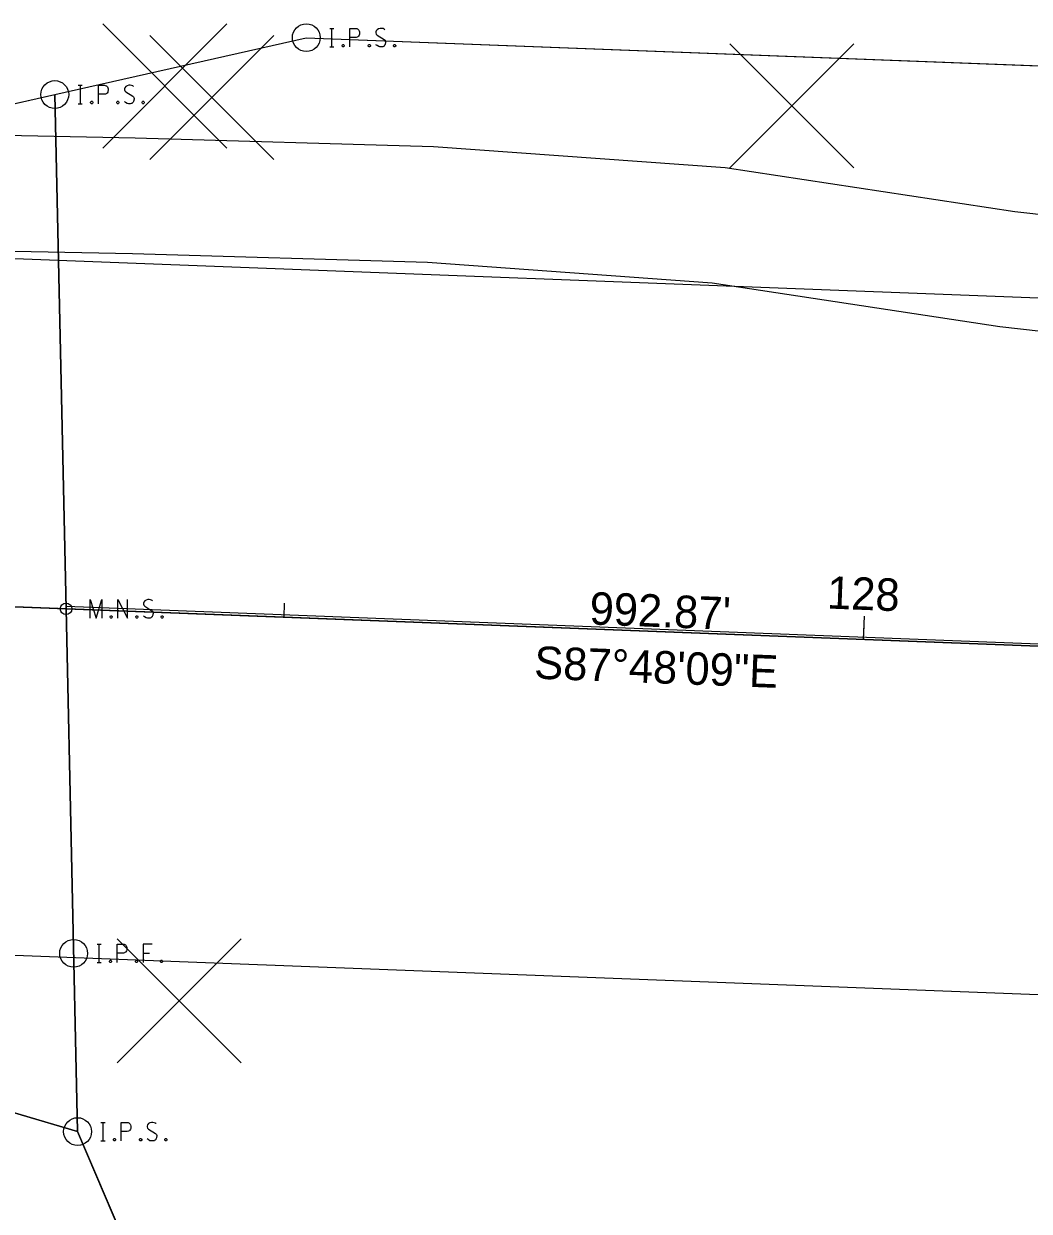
# Model space of a CAD drawing. Extents: x 2003596 to 2006933, y 570827 to 573780.
# Drawn here: x 2005461.8 to 2005548.5, y 572566.7 to 572669.1 of the extents above; entities that cross this region are included whole.
import ezdxf

# ---------------------------------------------------------------- set-up
doc = ezdxf.new("R2010")
doc.units = 0
for name, color, linetype in [('DT_X_Contour_Major', 7, 'Continuous'), ('DT_X_Spot_Elev', 7, 'Continuous'), ('DT_X_TIN_Hull', 7, 'Continuous'), ('GE_X_Alignment', 7, 'Continuous'), ('GE_X_Alignment_1000_Bearings', 7, 'Continuous'), ('GE_X_Alignment_1000_Distances', 7, 'Continuous'), ('GE_X_Alignment_100_Bearings', 7, 'Continuous'), ('GE_X_Alignment_100_Distances', 7, 'Continuous'), ('GE_X_Alignment_100_Stations', 7, 'Continuous'), ('GE_X_Alignment_500_Bearings', 7, 'Continuous'), ('GE_X_Alignment_500_Distances', 7, 'Continuous'), ('GE_X_Alignment_500_Stations', 7, 'Continuous'), ('RW_X_CL', 7, 'Continuous'), ('RW_X_Esmt_SH', 7, 'Continuous'), ('SC_Scratch10', 7, 'Continuous'), ('SV_P_Mon_Cells_Set', 7, 'Continuous'), ('SV_X_Mon_Cells_Found', 7, 'Continuous'), ('UT_X_Overhead_Electric', 7, 'Continuous'), ('UT_X_Overhead_Telecom', 7, 'Continuous'), ('UT_X_Telecom', 7, 'Continuous')]:
    doc.layers.add(name, color=color, linetype=linetype)

msp = doc.modelspace()

# ---------------------------------------------------------------- linework, layer by layer
at = {"layer": 'DT_X_Contour_Major'}
for points in [[(2005467.51, 572617.87), (2005467.51, 572619.47), (2005468.02, 572617.87), (2005468.51, 572619.47), (2005468.51, 572617.87)], [(2005469.88, 572617.87), (2005469.88, 572619.47), (2005470.71, 572617.87), (2005470.71, 572619.47)], [(2005472.86, 572619.35), (2005472.84, 572619.38), (2005472.8, 572619.41), (2005472.71, 572619.44), (2005472.58, 572619.47), (2005472.5, 572619.47), (2005472.46, 572619.47), (2005472.32, 572619.43), (2005472.2, 572619.35), (2005472.12, 572619.25), (2005472.1, 572619.15), (2005472.1, 572619.08), (2005472.12, 572618.98), (2005472.21, 572618.89), (2005472.82, 572618.51), (2005472.87, 572618.46), (2005472.89, 572618.41), (2005472.92, 572618.33), (2005472.92, 572618.26), (2005472.9, 572618.18), (2005472.89, 572618.13), (2005472.87, 572618.07), (2005472.85, 572618.02), (2005472.83, 572617.98), (2005472.79, 572617.94), (2005472.76, 572617.92), (2005472.72, 572617.89), (2005472.68, 572617.88), (2005472.58, 572617.87), (2005472.43, 572617.87), (2005472.33, 572617.89), (2005472.19, 572617.98), (2005472.1, 572618.06)], [(2005469.28, 572618.08), (2005469.33, 572618.08), (2005469.37, 572618.06), (2005469.4, 572618.01), (2005469.4, 572617.94), (2005469.37, 572617.89), (2005469.33, 572617.87), (2005469.28, 572617.87), (2005469.24, 572617.89), (2005469.21, 572617.94), (2005469.21, 572618.01), (2005469.24, 572618.06), (2005469.28, 572618.08)], [(2005471.49, 572618.08), (2005471.55, 572618.08), (2005471.58, 572618.06), (2005471.61, 572618.01), (2005471.61, 572617.94), (2005471.58, 572617.89), (2005471.55, 572617.87), (2005471.49, 572617.87), (2005471.46, 572617.89), (2005471.43, 572617.94), (2005471.43, 572618.01), (2005471.46, 572618.06), (2005471.49, 572618.08)], [(2005473.68, 572618.08), (2005473.73, 572618.08), (2005473.76, 572618.06), (2005473.8, 572618.01), (2005473.8, 572617.94), (2005473.76, 572617.89), (2005473.73, 572617.87), (2005473.68, 572617.87), (2005473.64, 572617.89), (2005473.61, 572617.94), (2005473.61, 572618.01), (2005473.64, 572618.06), (2005473.68, 572618.08)]]:
    msp.add_lwpolyline(points, dxfattribs=at)
msp.add_circle((2005465.42, 572618.67), 0.497, dxfattribs=at)
at = {"layer": 'DT_X_Spot_Elev'}
for p, q in [((2005464.45, 572663.01), (2005486.13, 572667.91)), ((2005486.13, 572667.91), (2005566.08, 572664.84)), ((2005410.42, 572650.8), (2005464.45, 572663.01)), ((2005464.45, 572663.01), (2005465.42, 572618.67)), ((2005465.42, 572618.67), (2005464.45, 572663.01)), ((2005465.42, 572618.67), (2005409.27, 572620.82)), ((2005409.27, 572620.82), (2005465.42, 572618.67)), ((2005634.11, 572612.2), (2005465.42, 572618.67)), ((2005465.42, 572618.67), (2005654.09, 572611.43)), ((2005466.41, 572573.6), (2005465.42, 572618.67)), ((2005465.42, 572618.67), (2005466.41, 572573.6)), ((2005466.41, 572573.6), (2005408.12, 572590.85)), ((2005490.38, 572517.64), (2005466.41, 572573.6))]:
    msp.add_line(p, q, dxfattribs=at)
at = {"layer": 'DT_X_TIN_Hull'}
for p, q in [((2005468.58, 572669.09), (2005479.28, 572658.39)), ((2005479.28, 572669.09), (2005468.58, 572658.39)), ((2005472.63, 572668.11), (2005483.33, 572657.42)), ((2005483.33, 572668.11), (2005472.63, 572657.42)), ((2005522.64, 572667.37), (2005533.34, 572656.68)), ((2005533.34, 572667.37), (2005522.64, 572656.68)), ((2005473.93, 572663.74), (2005473.93, 572663.74)), ((2005477.98, 572662.76), (2005477.98, 572662.76)), ((2005527.99, 572662.02), (2005527.99, 572662.02)), ((2005469.83, 572590.22), (2005480.53, 572579.53)), ((2005480.53, 572590.22), (2005469.83, 572579.53)), ((2005475.18, 572584.88), (2005475.18, 572584.88))]:
    msp.add_line(p, q, dxfattribs=at)
at = {"layer": 'GE_X_Alignment'}
msp.add_line((2005031.48, 572635.32), (2006023.62, 572597.25), dxfattribs=at)
at = {"layer": 'GE_X_Alignment_100_Stations'}
for p, q in [((2005484.22, 572617.95), (2005484.26, 572619.15)), ((2005534.18, 572616.03), (2005534.26, 572618.03))]:
    msp.add_line(p, q, dxfattribs=at)
at = {"layer": 'GE_X_Alignment_500_Stations'}
msp.add_line((2005534.18, 572616.03), (2005534.23, 572617.23), dxfattribs=at)
at = {"layer": 'RW_X_CL'}
msp.add_line((2006023.62, 572597.25), (2005031.48, 572635.32), dxfattribs=at)
at = {"layer": 'RW_X_Esmt_SH'}
for p, q in [((2005034.78, 572665.22), (2006024.45, 572627.24)), ((2005028.18, 572605.42), (2006022.8, 572567.26))]:
    msp.add_line(p, q, dxfattribs=at)
at = {"layer": 'SC_Scratch10'}
msp.add_line((2006023.71, 572597.25), (2005465.42, 572618.88), dxfattribs=at)
at = {"layer": 'SV_P_Mon_Cells_Set'}
for points in [[(2005488.15, 572668.71), (2005488.51, 572668.71)], [(2005488.33, 572667.11), (2005488.33, 572668.71)], [(2005489.9, 572667.11), (2005489.9, 572668.71), (2005490.42, 572668.71), (2005490.48, 572668.7), (2005490.56, 572668.67), (2005490.59, 572668.65), (2005490.62, 572668.62), (2005490.67, 572668.56), (2005490.7, 572668.5), (2005490.72, 572668.4), (2005490.72, 572668.25), (2005490.71, 572668.2), (2005490.69, 572668.12), (2005490.64, 572668.03), (2005490.6, 572667.99), (2005490.57, 572667.97), (2005490.51, 572667.94), (2005490.42, 572667.93), (2005489.9, 572667.93)], [(2005492.9, 572668.6), (2005492.88, 572668.62), (2005492.85, 572668.65), (2005492.75, 572668.69), (2005492.63, 572668.71), (2005492.54, 572668.71), (2005492.51, 572668.71), (2005492.36, 572668.67), (2005492.24, 572668.6), (2005492.17, 572668.5), (2005492.14, 572668.4), (2005492.14, 572668.32), (2005492.17, 572668.22), (2005492.25, 572668.13), (2005492.86, 572667.76), (2005492.92, 572667.7), (2005492.94, 572667.65), (2005492.96, 572667.58), (2005492.96, 572667.5), (2005492.95, 572667.43), (2005492.94, 572667.38), (2005492.92, 572667.31), (2005492.89, 572667.26), (2005492.87, 572667.23), (2005492.84, 572667.19), (2005492.81, 572667.16), (2005492.76, 572667.14), (2005492.73, 572667.13), (2005492.63, 572667.11), (2005492.47, 572667.11), (2005492.38, 572667.14), (2005492.23, 572667.23), (2005492.14, 572667.3)], [(2005488.15, 572667.11), (2005488.51, 572667.11)], [(2005489.29, 572667.33), (2005489.34, 572667.33), (2005489.38, 572667.3), (2005489.41, 572667.25), (2005489.41, 572667.19), (2005489.38, 572667.14), (2005489.34, 572667.11), (2005489.29, 572667.11), (2005489.26, 572667.14), (2005489.22, 572667.19), (2005489.22, 572667.25), (2005489.26, 572667.3), (2005489.29, 572667.33)], [(2005491.54, 572667.33), (2005491.59, 572667.33), (2005491.63, 572667.3), (2005491.66, 572667.25), (2005491.66, 572667.19), (2005491.63, 572667.14), (2005491.59, 572667.11), (2005491.54, 572667.11), (2005491.5, 572667.14), (2005491.47, 572667.19), (2005491.47, 572667.25), (2005491.5, 572667.3), (2005491.54, 572667.33)], [(2005493.72, 572667.33), (2005493.78, 572667.33), (2005493.81, 572667.3), (2005493.84, 572667.25), (2005493.84, 572667.19), (2005493.81, 572667.14), (2005493.78, 572667.11), (2005493.72, 572667.11), (2005493.69, 572667.14), (2005493.65, 572667.19), (2005493.65, 572667.25), (2005493.69, 572667.3), (2005493.72, 572667.33)], [(2005466.47, 572663.81), (2005466.82, 572663.81)], [(2005466.65, 572662.21), (2005466.65, 572663.81)], [(2005468.21, 572662.21), (2005468.21, 572663.81), (2005468.74, 572663.81), (2005468.8, 572663.8), (2005468.87, 572663.77), (2005468.91, 572663.75), (2005468.94, 572663.72), (2005468.98, 572663.66), (2005469.02, 572663.6), (2005469.04, 572663.5), (2005469.04, 572663.35), (2005469.03, 572663.3), (2005469.01, 572663.22), (2005468.96, 572663.13), (2005468.92, 572663.09), (2005468.88, 572663.07), (2005468.83, 572663.04), (2005468.74, 572663.03), (2005468.21, 572663.03)], [(2005471.22, 572663.7), (2005471.2, 572663.72), (2005471.17, 572663.75), (2005471.07, 572663.79), (2005470.95, 572663.81), (2005470.86, 572663.81), (2005470.82, 572663.81), (2005470.68, 572663.77), (2005470.56, 572663.7), (2005470.48, 572663.6), (2005470.46, 572663.5), (2005470.46, 572663.42), (2005470.48, 572663.32), (2005470.57, 572663.23), (2005471.18, 572662.86), (2005471.23, 572662.8), (2005471.25, 572662.75), (2005471.28, 572662.68), (2005471.28, 572662.6), (2005471.26, 572662.53), (2005471.25, 572662.48), (2005471.23, 572662.41), (2005471.21, 572662.36), (2005471.19, 572662.33), (2005471.15, 572662.29), (2005471.12, 572662.26), (2005471.08, 572662.24), (2005471.04, 572662.23), (2005470.95, 572662.21), (2005470.79, 572662.21), (2005470.69, 572662.24), (2005470.55, 572662.33), (2005470.46, 572662.4)], [(2005466.47, 572662.21), (2005466.82, 572662.21)], [(2005467.61, 572662.43), (2005467.66, 572662.43), (2005467.69, 572662.4), (2005467.73, 572662.35), (2005467.73, 572662.29), (2005467.69, 572662.24), (2005467.66, 572662.21), (2005467.61, 572662.21), (2005467.57, 572662.24), (2005467.54, 572662.29), (2005467.54, 572662.35), (2005467.57, 572662.4), (2005467.61, 572662.43)], [(2005469.85, 572662.43), (2005469.91, 572662.43), (2005469.94, 572662.4), (2005469.98, 572662.35), (2005469.98, 572662.29), (2005469.94, 572662.24), (2005469.91, 572662.21), (2005469.85, 572662.21), (2005469.82, 572662.24), (2005469.79, 572662.29), (2005469.79, 572662.35), (2005469.82, 572662.4), (2005469.85, 572662.43)], [(2005472.04, 572662.43), (2005472.09, 572662.43), (2005472.12, 572662.4), (2005472.16, 572662.35), (2005472.16, 572662.29), (2005472.12, 572662.24), (2005472.09, 572662.21), (2005472.04, 572662.21), (2005472, 572662.24), (2005471.97, 572662.29), (2005471.97, 572662.35), (2005472, 572662.4), (2005472.04, 572662.43)], [(2005468.43, 572574.4), (2005468.78, 572574.4)], [(2005468.61, 572572.8), (2005468.61, 572574.4)], [(2005470.17, 572572.8), (2005470.17, 572574.4), (2005470.7, 572574.4), (2005470.76, 572574.39), (2005470.83, 572574.36), (2005470.87, 572574.34), (2005470.9, 572574.31), (2005470.94, 572574.25), (2005470.98, 572574.19), (2005471, 572574.08), (2005471, 572573.93), (2005470.99, 572573.88), (2005470.97, 572573.81), (2005470.92, 572573.72), (2005470.88, 572573.68), (2005470.85, 572573.66), (2005470.79, 572573.63), (2005470.7, 572573.62), (2005470.17, 572573.62)], [(2005473.18, 572574.29), (2005473.16, 572574.31), (2005473.13, 572574.34), (2005473.03, 572574.37), (2005472.91, 572574.4), (2005472.82, 572574.4), (2005472.79, 572574.4), (2005472.64, 572574.36), (2005472.52, 572574.29), (2005472.44, 572574.19), (2005472.42, 572574.08), (2005472.42, 572574.01), (2005472.44, 572573.91), (2005472.53, 572573.82), (2005473.14, 572573.44), (2005473.19, 572573.39), (2005473.21, 572573.34), (2005473.24, 572573.27), (2005473.24, 572573.19), (2005473.23, 572573.11), (2005473.21, 572573.06), (2005473.19, 572573), (2005473.17, 572572.95), (2005473.15, 572572.91), (2005473.12, 572572.88), (2005473.08, 572572.85), (2005473.04, 572572.82), (2005473.01, 572572.81), (2005472.91, 572572.8), (2005472.75, 572572.8), (2005472.65, 572572.82), (2005472.51, 572572.91), (2005472.42, 572572.99)], [(2005468.43, 572572.8), (2005468.78, 572572.8)], [(2005469.57, 572573.01), (2005469.62, 572573.01), (2005469.65, 572572.99), (2005469.69, 572572.94), (2005469.69, 572572.88), (2005469.65, 572572.82), (2005469.62, 572572.8), (2005469.57, 572572.8), (2005469.53, 572572.82), (2005469.5, 572572.88), (2005469.5, 572572.94), (2005469.53, 572572.99), (2005469.57, 572573.01)], [(2005471.82, 572573.01), (2005471.87, 572573.01), (2005471.9, 572572.99), (2005471.94, 572572.94), (2005471.94, 572572.88), (2005471.9, 572572.82), (2005471.87, 572572.8), (2005471.82, 572572.8), (2005471.78, 572572.82), (2005471.75, 572572.88), (2005471.75, 572572.94), (2005471.78, 572572.99), (2005471.82, 572573.01)], [(2005474, 572573.01), (2005474.05, 572573.01), (2005474.09, 572572.99), (2005474.12, 572572.94), (2005474.12, 572572.88), (2005474.09, 572572.82), (2005474.05, 572572.8), (2005474, 572572.8), (2005473.96, 572572.82), (2005473.93, 572572.88), (2005473.93, 572572.94), (2005473.96, 572572.99), (2005474, 572573.01)]]:
    msp.add_lwpolyline(points, dxfattribs=at)
for centre in [(2005486.13, 572667.91), (2005464.45, 572663.01), (2005466.41, 572573.6)]:
    msp.add_circle(centre, 1.2, dxfattribs=at)
at = {"layer": 'SV_X_Mon_Cells_Found'}
for points in [[(2005468.09, 572589.77), (2005468.44, 572589.77)], [(2005468.27, 572588.17), (2005468.27, 572589.77)], [(2005469.83, 572588.17), (2005469.83, 572589.77), (2005470.36, 572589.77), (2005470.42, 572589.76), (2005470.49, 572589.73), (2005470.53, 572589.71), (2005470.56, 572589.68), (2005470.6, 572589.62), (2005470.64, 572589.56), (2005470.66, 572589.46), (2005470.66, 572589.31), (2005470.65, 572589.25), (2005470.62, 572589.18), (2005470.58, 572589.09), (2005470.54, 572589.05), (2005470.5, 572589.03), (2005470.45, 572589), (2005470.36, 572588.99), (2005469.83, 572588.99)], [(2005472.84, 572589.77), (2005472.08, 572589.77), (2005472.08, 572588.17)], [(2005468.09, 572588.17), (2005468.44, 572588.17)], [(2005469.22, 572588.39), (2005469.28, 572588.39), (2005469.31, 572588.36), (2005469.35, 572588.31), (2005469.35, 572588.25), (2005469.31, 572588.2), (2005469.28, 572588.17), (2005469.22, 572588.17), (2005469.19, 572588.2), (2005469.16, 572588.25), (2005469.16, 572588.31), (2005469.19, 572588.36), (2005469.22, 572588.39)], [(2005471.47, 572588.39), (2005471.53, 572588.39), (2005471.56, 572588.36), (2005471.59, 572588.31), (2005471.59, 572588.25), (2005471.56, 572588.2), (2005471.53, 572588.17), (2005471.47, 572588.17), (2005471.44, 572588.2), (2005471.41, 572588.25), (2005471.41, 572588.31), (2005471.44, 572588.36), (2005471.47, 572588.39)], [(2005472.08, 572588.99), (2005472.62, 572588.99)], [(2005473.62, 572588.39), (2005473.68, 572588.39), (2005473.71, 572588.36), (2005473.74, 572588.31), (2005473.74, 572588.25), (2005473.71, 572588.2), (2005473.68, 572588.17), (2005473.62, 572588.17), (2005473.59, 572588.2), (2005473.56, 572588.25), (2005473.56, 572588.31), (2005473.59, 572588.36), (2005473.62, 572588.39)]]:
    msp.add_lwpolyline(points, dxfattribs=at)
msp.add_circle((2005466.07, 572588.97), 1.2, dxfattribs=at)
at = {"layer": 'UT_X_Overhead_Electric'}
for points in [[(2005410.42, 572650.8), (2005464.45, 572663.01), (2005486.13, 572667.91), (2005566.08, 572664.84), (2005635.26, 572642.17)], [(2005408.12, 572590.85), (2005466.41, 572573.6), (2005490.38, 572517.64), (2005565.32, 572514.76), (2005606.83, 572553.2), (2005652.37, 572566.46)]]:
    msp.add_lwpolyline(points, dxfattribs=at)
at = {"layer": 'UT_X_Overhead_Telecom'}
msp.add_lwpolyline([(2005410.42, 572650.8), (2005464.45, 572663.01), (2005486.13, 572667.91), (2005566.08, 572664.84), (2005635.26, 572642.17)], dxfattribs=at)
at = {"layer": 'UT_X_Telecom'}
for points in [[(2005147.76, 572660.26), (2005421.1, 572658.32), (2005446.17, 572659.8), (2005471.38, 572659.28), (2005497.09, 572658.54), (2005522.25, 572656.73), (2005547.24, 572652.92), (2005571.87, 572650.16), (2005596.85, 572649.37), (2005621.79, 572646.67), (2006021.03, 572631.61)], [(2005147.98, 572650.26), (2005421.36, 572648.31), (2005446.36, 572649.8), (2005471.14, 572649.29), (2005496.59, 572648.55), (2005521.14, 572646.78), (2005545.93, 572643), (2005571.15, 572640.18), (2005596.15, 572639.39), (2005621.06, 572636.69), (2006021.19, 572621.6)]]:
    msp.add_lwpolyline(points, dxfattribs=at)

# ---------------------------------------------------------------- texts
at = {"layer": 'GE_X_Alignment_1000_Bearings'}
msp.add_text('S87°48\'09"E', height=2.8, rotation=357.8026, dxfattribs=at).set_placement((2005505.75, 572612.66))
at = {"layer": 'GE_X_Alignment_1000_Distances'}
msp.add_text("992.87'", height=2.8, rotation=357.8026, dxfattribs=at).set_placement((2005510.52, 572617.33))
at = {"layer": 'GE_X_Alignment_100_Bearings'}
msp.add_text('S87°48\'09"E', height=2.8, rotation=357.8026, dxfattribs=at).set_placement((2005505.75, 572612.66))
at = {"layer": 'GE_X_Alignment_100_Distances'}
msp.add_text("992.87'", height=2.8, rotation=357.8026, dxfattribs=at).set_placement((2005510.52, 572617.33))
at = {"layer": 'GE_X_Alignment_100_Stations'}
msp.add_text('128', height=2.8, rotation=357.8026, dxfattribs=at).set_placement((2005531, 572618.7))
at = {"layer": 'GE_X_Alignment_500_Bearings'}
msp.add_text('S87°48\'09"E', height=2.8, rotation=357.8026, dxfattribs=at).set_placement((2005505.75, 572612.66))
at = {"layer": 'GE_X_Alignment_500_Distances'}
msp.add_text("992.87'", height=2.8, rotation=357.8026, dxfattribs=at).set_placement((2005510.52, 572617.33))

doc.saveas('drawing.dxf')
